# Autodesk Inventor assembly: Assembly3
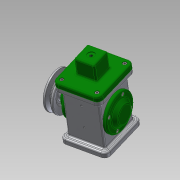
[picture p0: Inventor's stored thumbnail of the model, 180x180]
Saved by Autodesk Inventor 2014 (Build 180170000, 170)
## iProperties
Created: 2017-08
Part Number: Assembly3
Document SubType Name: Assembly
Designer: user
Author: user
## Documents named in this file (18)
- C:\Users\user\Desktop\470808V1024\Assembly3.iam
- C:\Users\user\Desktop\470808V1024\본체.ipt
- C:\Users\user\Desktop\470808V1024\E-링.ipt
- C:\Users\user\Desktop\470808V1024\V-벨트풀리.ipt
- C:\Users\user\Desktop\470808V1024\덮개.ipt
- C:\Users\user\Desktop\470808V1024\뒤커버.ipt
- C:\Users\user\Desktop\470808V1024\링크.ipt
- C:\Users\user\Desktop\470808V1024\베어링 17 x 40 x 12.ipt
- C:\Users\user\Desktop\470808V1024\볼트 M4 x 8.ipt
- C:\Users\user\Desktop\470808V1024\볼트 M4 x 10.ipt
- C:\Users\user\Desktop\470808V1024\슬라이더.ipt
- C:\Users\user\Desktop\470808V1024\앞커버.ipt
- C:\Users\user\Desktop\470808V1024\오일 실 17 30 8.ipt
- C:\Users\user\Desktop\470808V1024\와셔 4x16.ipt
- C:\Users\user\Desktop\470808V1024\클레비스 핀 6 x 22.ipt
- 클레비스 핀 6 x 22.ipt
- C:\Users\user\Desktop\470808V1024\키 4 x 4 x 12.ipt
- C:\Users\user\Desktop\470808V1024\편심축.ipt
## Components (2 placed, 2 different names)
1. E-링:1 — Mate:55, Mate:56
2. V-벨트풀리:1 — Mate:4, Mate:5, Mate:6, Mate:59
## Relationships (6: Mate 6)
- Mate:4: V-벨트풀리:1
- Mate:5: V-벨트풀리:1
- Mate:6: V-벨트풀리:1
- Mate:55: E-링:1
- Mate:56: E-링:1
- Mate:59: V-벨트풀리:1
